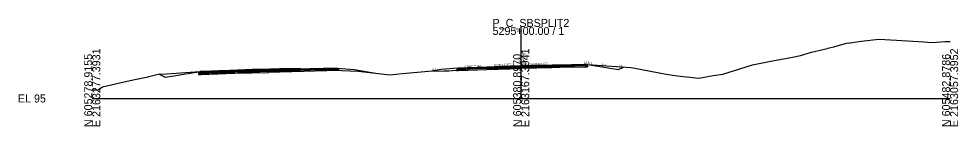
# Model space of a CAD drawing. Extents: x -26 to 1303, y -10 to 12033.
# Drawn here: x -25.7 to 302.8, y 7990.3 to 8027.8 of the extents above; entities that cross this region are included whole.
import ezdxf

# ---------------------------------------------------------------- set-up
doc = ezdxf.new("R2010")
doc.units = 0
for name, color, linetype in [('RD_GPK_XS_Cell', 7, 'Continuous'), ('RD_XS_Base', 7, 'Continuous'), ('RD_XS_ExGround', 7, 'Continuous'), ('RD_XS_ExPaveRet', 7, 'Continuous'), ('RD_XS_Greenside', 7, 'Continuous'), ('RD_XS_Pave', 7, 'Continuous'), ('RD_XS_PaveOvlay_CP', 7, 'Continuous'), ('RD_XS_TieSlope', 7, 'Continuous'), ('RD_XS_TX_Elev_EX', 7, 'Continuous'), ('RD_XS_TX_Elev_PR', 7, 'Continuous'), ('RD_XS_TX_ShdSlope', 7, 'Continuous'), ('RD_XS_TX_Slope', 7, 'Continuous')]:
    doc.layers.add(name, color=color, linetype=linetype)

msp = doc.modelspace()

# ---------------------------------------------------------------- linework, layer by layer
at = {"layer": 'RD_GPK_XS_Cell'}
for p, q in [((150, 8000), (150, 8025)), ((0, 8000), (150, 8000)), ((150, 8000), (300, 8000))]:
    msp.add_line(p, q, dxfattribs=at)
at = {"layer": 'RD_XS_Base'}
for p, q in [((61.6, 8009.63), (49.91, 8009.33)), ((61.6, 8009.63), (86.1, 8010.27)), ((61.6, 8009.13), (61.6, 8009.79)), ((61.6, 8009.79), (61.6, 8009.79)), ((61.6, 8009.79), (61.6, 8009.79)), ((61.6, 8009.79), (61.6, 8009.63)), ((86.1, 8009.77), (61.6, 8009.13)), ((61.6, 8009.63), (61.6, 8009.63)), ((61.6, 8009.13), (61.6, 8009.63)), ((61.6, 8009.63), (61.6, 8009.63)), ((61.6, 8009.63), (61.6, 8009.63)), ((85.6, 8010.26), (85.6, 8010.26)), ((85.6, 8010.26), (85.6, 8010.26)), ((85.6, 8010.26), (85.6, 8010.26)), ((85.6, 8009.76), (85.6, 8009.76)), ((85.6, 8009.76), (85.6, 8009.76)), ((86.1, 8010.27), (86.1, 8009.77)), ((86.1, 8010.24), (86.1, 8010.24)), ((128, 8010.23), (127.5, 8010.21)), ((127.5, 8010.21), (127.5, 8010.21)), ((127.5, 8010.21), (127.5, 8009.71)), ((127.5, 8009.71), (128, 8009.73)), ((138, 8010.63), (128, 8010.23)), ((128, 8010.23), (128, 8010.23)), ((128, 8009.73), (138, 8010.13)), ((128, 8009.73), (128, 8009.73)), ((136, 8010.55), (136, 8010.55)), ((136, 8010.05), (136, 8010.05)), ((150, 8010.97), (138, 8010.63)), ((138, 8010.13), (150, 8010.47)), ((150, 8010.97), (172, 8011.58)), ((150, 8010.47), (150, 8011.12)), ((150, 8011.12), (150, 8011.12)), ((150, 8011.12), (150, 8011.12)), ((150, 8011.12), (150, 8010.97)), ((172.5, 8011.1), (150, 8010.47)), ((150, 8010.97), (150, 8010.97)), ((150, 8010.47), (150, 8010.97)), ((150, 8010.97), (150, 8010.97)), ((150, 8010.97), (150, 8010.97)), ((150, 8010.47), (150, 8010.47)), ((162, 8011.3), (162, 8011.3)), ((162, 8011.3), (162, 8011.3)), ((162, 8010.8), (162, 8010.8)), ((162, 8010.8), (162, 8010.8)), ((172, 8011.58), (172, 8011.58)), ((172.5, 8011.6), (172.5, 8011.1)), ((172.5, 8011.56), (172.5, 8011.56)), ((37.6, 8008.84), (37.1, 8008.82)), ((37.1, 8008.82), (37.1, 8008.82)), ((37.1, 8008.82), (37.1, 8008.32)), ((37.1, 8008.32), (37.6, 8008.34)), ((38.24, 8008.87), (37.6, 8008.84)), ((37.6, 8008.84), (37.6, 8008.84)), ((37.6, 8008.34), (38.24, 8008.37)), ((37.6, 8008.34), (37.6, 8008.34)), ((49.6, 8009.32), (38.24, 8008.87)), ((38.24, 8008.37), (49.6, 8008.82)), ((49.91, 8009.33), (49.6, 8009.32)), ((49.6, 8008.82), (49.91, 8008.83)), ((49.91, 8008.83), (61.6, 8009.13)), ((61.6, 8009.13), (61.6, 8009.13))]:
    msp.add_line(p, q, dxfattribs=at)
at = {"layer": 'RD_XS_ExGround'}
msp.add_lwpolyline([(0, 8002.98), (1.27, 8002.97), (1.79, 8002.94), (2.56, 8003.39), (3.63, 8004.01), (8.65, 8005.22), (14.26, 8006.5), (18.92, 8007.45), (19.53, 8007.61), (19.76, 8007.64), (23.1, 8008.46), (25.98, 8008.63), (37.67, 8009.37), (44.28, 8009.61), (48.16, 8009.75), (57.32, 8010.14), (58.42, 8010.18), (65.46, 8010.34), (72.88, 8010.49), (84.36, 8009.91), (92.98, 8009.5), (99.07, 8008.8), (104.05, 8008.26), (108.55, 8008.68), (117.55, 8009.5), (122.98, 8009.62), (124.67, 8009.65), (131.9, 8010.37), (138.22, 8010.97), (143, 8011.14), (146.43, 8011.24), (153.81, 8011.47), (153.86, 8011.48), (154.66, 8011.48), (155.42, 8011.5), (160.87, 8011.6), (163.68, 8011.67), (172.51, 8011.85), (173.15, 8011.86), (181.75, 8011.27), (188.35, 8010.82), (189.7, 8010.58), (200.68, 8008.5), (204.72, 8007.94), (212.14, 8007.13), (217.1, 8007.97), (220.55, 8008.49), (224.58, 8009.76), (230.9, 8011.72), (237.94, 8013.21), (244.87, 8014.47), (247.69, 8015.05), (251.58, 8016.14), (256.52, 8017.34), (257.1, 8017.47), (257.29, 8017.53), (259.36, 8018.03), (263.8, 8019.29), (264.81, 8019.48), (265.07, 8019.5), (268.87, 8019.97), (275.08, 8020.69), (281.29, 8020.32), (290.86, 8019.78), (293.66, 8019.61), (298.28, 8019.86), (300, 8019.96)], dxfattribs=at)
at = {"layer": 'RD_XS_ExPaveRet'}
for points in [[(65.46, 8010.34), (58.49, 8010.18), (58.42, 8010.18), (57.72, 8010.15), (57.32, 8010.14), (56.03, 8010.08), (48.16, 8009.75), (45.46, 8009.65), (44.28, 8009.61), (38.77, 8009.41), (37.67, 8009.37), (37.67, 8009.37), (37.67, 8009.15), (37.67, 8008.62), (37.67, 8008.62), (38.77, 8008.66), (44.28, 8008.86), (45.46, 8008.9), (48.16, 8009), (56.03, 8009.33), (57.32, 8009.39), (57.72, 8009.4), (58.42, 8009.43), (58.49, 8009.43), (65.46, 8009.59), (68.12, 8009.65), (72.88, 8009.74), (72.88, 8010.34), (72.88, 8010.49), (68.12, 8010.4), (65.46, 8010.34)], [(65.46, 8010.34), (58.49, 8010.18), (58.42, 8010.18), (57.72, 8010.15), (57.32, 8010.14), (56.03, 8010.08), (48.16, 8009.75), (45.46, 8009.65), (44.28, 8009.61), (38.77, 8009.41), (37.67, 8009.37), (37.67, 8009.15), (37.67, 8008.62), (38.77, 8008.66), (44.28, 8008.86), (45.46, 8008.9), (48.16, 8009), (56.03, 8009.33), (57.32, 8009.39), (57.72, 8009.4), (58.42, 8009.43), (58.49, 8009.43), (65.46, 8009.59), (68.12, 8009.65), (72.88, 8009.74), (72.88, 8010.34), (72.88, 8010.49), (68.12, 8010.4), (65.46, 8010.34)], [(173.15, 8011.86), (173.15, 8011.86), (173.15, 8011.86), (173.15, 8011.11), (173.15, 8011.11), (172.51, 8011.1), (172.51, 8011.1), (163.68, 8010.92), (163.68, 8010.92), (160.87, 8010.85), (160.87, 8010.85), (155.42, 8010.75), (155.42, 8010.75), (155.42, 8010.75), (154.66, 8010.73), (154.66, 8010.73), (153.86, 8010.73), (153.81, 8010.72), (153.81, 8010.72), (146.43, 8010.49), (146.43, 8010.49), (143, 8010.39), (138.22, 8010.22), (138.22, 8010.22), (138.22, 8010.22), (138.22, 8010.22), (138.22, 8010.97), (138.22, 8010.97), (138.22, 8010.97), (138.22, 8010.97), (138.22, 8010.97), (143, 8011.14), (146.43, 8011.24), (146.43, 8011.24), (153.81, 8011.47), (153.81, 8011.47), (153.86, 8011.48), (154.66, 8011.48), (154.66, 8011.48), (155.42, 8011.5), (155.42, 8011.5), (155.42, 8011.5), (160.87, 8011.6), (160.87, 8011.6), (163.68, 8011.67), (163.68, 8011.67), (172.51, 8011.85), (172.51, 8011.85), (173.15, 8011.86)], [(172.51, 8011.85), (163.68, 8011.67), (160.87, 8011.6), (155.42, 8011.5), (154.66, 8011.48), (153.86, 8011.48), (153.81, 8011.47), (146.43, 8011.24), (143, 8011.14), (138.22, 8010.97), (138.22, 8010.97), (138.22, 8010.22), (138.22, 8010.22), (143, 8010.39), (146.43, 8010.49), (153.81, 8010.72), (153.86, 8010.73), (154.66, 8010.73), (155.42, 8010.75), (160.87, 8010.85), (163.68, 8010.92), (172.51, 8011.1), (173.15, 8011.11), (173.15, 8011.86), (172.51, 8011.85)]]:
    msp.add_lwpolyline(points, dxfattribs=at)
at = {"layer": 'RD_XS_Greenside'}
for p, q in [((91.6, 8010.09), (99.92, 8008.71)), ((122, 8010.07), (118.74, 8009.53)), ((174, 8011.74), (184, 8010.07)), ((184, 8010.07), (185.83, 8010.99)), ((25.6, 8007.33), (23.33, 8008.47)), ((35.6, 8009), (25.6, 8007.33))]:
    msp.add_line(p, q, dxfattribs=at)
at = {"layer": 'RD_XS_Pave'}
for p, q in [((38.24, 8009.18), (49.6, 8009.64)), ((49.6, 8009.64), (49.91, 8009.65)), ((49.91, 8009.65), (61.6, 8009.95)), ((61.6, 8009.79), (49.91, 8009.49)), ((49.91, 8009.49), (61.6, 8009.79)), ((61.6, 8009.63), (49.91, 8009.33)), ((85.6, 8010.57), (61.6, 8009.95)), ((85.6, 8010.41), (61.6, 8009.79)), ((61.6, 8009.79), (85.6, 8010.41)), ((61.6, 8009.63), (85.6, 8010.26)), ((61.6, 8009.95), (61.6, 8009.95)), ((61.6, 8009.79), (61.6, 8009.79)), ((61.6, 8009.79), (61.6, 8009.79)), ((61.6, 8009.79), (61.6, 8009.63)), ((61.6, 8009.79), (61.6, 8009.79)), ((61.6, 8009.63), (61.6, 8009.79)), ((61.6, 8009.79), (61.6, 8009.79)), ((61.6, 8009.79), (61.6, 8009.79)), ((61.6, 8009.63), (61.6, 8009.63)), ((61.6, 8009.63), (61.6, 8009.63)), ((85.6, 8010.41), (85.6, 8010.57)), ((85.6, 8010.57), (85.6, 8010.57)), ((85.6, 8010.57), (85.6, 8010.57)), ((85.6, 8010.57), (85.6, 8010.57)), ((85.6, 8010.26), (85.6, 8010.41)), ((85.6, 8010.41), (85.6, 8010.41)), ((85.6, 8010.41), (85.6, 8010.41)), ((85.6, 8010.41), (85.6, 8010.41)), ((85.6, 8010.41), (85.6, 8010.41)), ((85.6, 8010.41), (85.6, 8010.41)), ((85.6, 8010.26), (85.6, 8010.26)), ((85.6, 8010.26), (85.6, 8010.26)), ((138, 8010.95), (128, 8010.55)), ((128, 8010.39), (138, 8010.79)), ((138, 8010.79), (128, 8010.39)), ((128, 8010.23), (138, 8010.63)), ((128, 8010.55), (128, 8010.55)), ((128, 8010.55), (128, 8010.39)), ((128, 8010.39), (128, 8010.39)), ((128, 8010.39), (128, 8010.23)), ((136, 8010.87), (136, 8010.87)), ((136, 8010.71), (136, 8010.71)), ((136, 8010.71), (136, 8010.71)), ((136, 8010.55), (136, 8010.55)), ((150, 8011.28), (138, 8010.95)), ((138, 8010.79), (150, 8011.12)), ((150, 8011.12), (138, 8010.79)), ((138, 8010.63), (150, 8010.97)), ((172, 8011.9), (150, 8011.28)), ((172, 8011.74), (150, 8011.12)), ((150, 8011.12), (172, 8011.74)), ((150, 8010.97), (172.5, 8011.6)), ((150, 8011.28), (150, 8011.28)), ((150, 8011.12), (150, 8011.12)), ((150, 8011.12), (150, 8011.12)), ((150, 8011.12), (150, 8010.97)), ((150, 8011.12), (150, 8011.12)), ((150, 8010.97), (150, 8011.12)), ((150, 8011.12), (150, 8011.12)), ((150, 8011.12), (150, 8011.12)), ((150, 8010.97), (150, 8010.97)), ((150, 8010.97), (150, 8010.97)), ((162, 8011.62), (162, 8011.62)), ((162, 8011.62), (162, 8011.62)), ((162, 8011.46), (162, 8011.46)), ((162, 8011.46), (162, 8011.46)), ((162, 8011.46), (162, 8011.46)), ((162, 8011.46), (162, 8011.46)), ((162, 8011.3), (162, 8011.3)), ((162, 8011.3), (162, 8011.3)), ((172, 8011.74), (172, 8011.9)), ((172, 8011.9), (172, 8011.9)), ((172, 8011.58), (172, 8011.74)), ((172, 8011.74), (172, 8011.74)), ((37.6, 8009.16), (38.24, 8009.18)), ((37.6, 8009), (37.6, 8009.16)), ((37.6, 8009.16), (37.6, 8009.16)), ((38.24, 8009.03), (37.6, 8009)), ((37.6, 8009), (38.24, 8009.03)), ((37.6, 8008.84), (37.6, 8009)), ((37.6, 8009), (37.6, 8009)), ((38.24, 8008.87), (37.6, 8008.84)), ((49.6, 8009.48), (38.24, 8009.03)), ((38.24, 8009.03), (49.6, 8009.48)), ((49.6, 8009.32), (38.24, 8008.87)), ((49.91, 8009.49), (49.6, 8009.48)), ((49.6, 8009.48), (49.91, 8009.49)), ((49.91, 8009.33), (49.6, 8009.32))]:
    msp.add_line(p, q, dxfattribs=at)
at = {"layer": 'RD_XS_PaveOvlay_CP'}
for p, q in [((38.24, 8009.18), (49.6, 8009.64)), ((49.6, 8009.64), (49.91, 8009.65)), ((49.91, 8009.65), (61.6, 8009.95)), ((85.6, 8010.57), (61.6, 8009.95)), ((61.6, 8009.95), (61.6, 8009.95)), ((85.6, 8010.57), (85.6, 8010.57)), ((85.6, 8010.57), (85.6, 8010.57)), ((138, 8010.95), (128, 8010.55)), ((136, 8010.87), (136, 8010.87)), ((150, 8011.28), (138, 8010.95)), ((172, 8011.9), (150, 8011.28)), ((150, 8011.28), (150, 8011.28)), ((162, 8011.62), (162, 8011.62)), ((162, 8011.62), (162, 8011.62)), ((37.6, 8009.16), (38.24, 8009.18))]:
    msp.add_line(p, q, dxfattribs=at)
at = {"layer": 'RD_XS_TieSlope'}
for p, q in [((85.6, 8010.57), (91.6, 8010.09)), ((128, 8010.55), (122, 8010.07)), ((172, 8011.9), (174, 8011.74)), ((37.6, 8009.16), (35.6, 8009))]:
    msp.add_line(p, q, dxfattribs=at)

# ---------------------------------------------------------------- texts
at = {"layer": 'RD_GPK_XS_Cell'}
for s, p in [('P_C_SBSPLIT2', (140, 8025)), ('5295+00.00 / 1', (140, 8022.2)), ('EL 95', (-26, 7998.6))]:
    msp.add_text(s, height=2.8, dxfattribs=at).set_placement(p)
for s, p in [('E 2163277.3931', (2.8, 7990)), ('E 2163167.3941', (152.8, 7990)), ('E 2163057.3952', (302.8, 7990)), ('N 605278.9155', (0, 7990)), ('N 605380.8970', (150, 7990)), ('N 605482.8786', (300, 7990))]:
    msp.add_text(s, height=2.8, rotation=90, dxfattribs=at).set_placement(p)
at = {"layer": 'RD_XS_TX_Elev_EX'}
msp.add_text('106.35', height=0.6, rotation=90, dxfattribs=at).set_placement((149.71, 8012.25))
at = {"layer": 'RD_XS_TX_Elev_PR'}
msp.add_text('106.28', height=1, rotation=90, dxfattribs=at).set_placement((151.42, 8011.73))
at = {"layer": 'RD_XS_TX_ShdSlope'}
msp.add_text('12.5:1', height=0.75, rotation=355.4261, dxfattribs=at).set_placement((171.84, 8012.2))
at = {"layer": 'RD_XS_TX_Slope'}
for s, rotation, p in [('6:1', 9.4642, (119.01, 8009.81)), ('0.040 FT./FT.', 2.2906, (130.15, 8010.76)), ('0.030 FT./FT.', 1.7184, (140.45, 8011.24)), ('0.030 FT./FT.', 1.7184, (153.16, 8011.55)), ('6:1', 350.5358, (178.13, 8011.43)), ('2:1', 26.5651, (184.26, 8010.61))]:
    msp.add_text(s, height=0.75, rotation=rotation, dxfattribs=at).set_placement(p)

doc.saveas('drawing.dxf')
